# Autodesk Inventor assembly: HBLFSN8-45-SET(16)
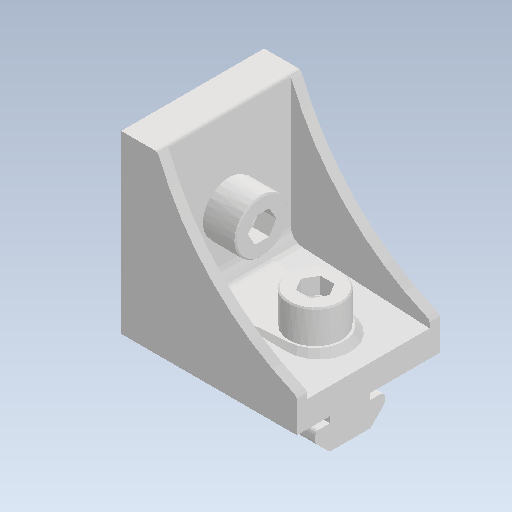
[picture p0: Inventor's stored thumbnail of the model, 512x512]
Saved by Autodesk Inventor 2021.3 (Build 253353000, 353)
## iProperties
Created: 2022-02
Part Number: HBLFSN8-45-SET(16)
Document SubType Name: Assembly
Designer: kengo
Author: kengo
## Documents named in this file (4)
- C:\Users\kengo\Documents\S2S_frame\SDC345\frame_misumi_ver12\HBLFSN8-45-SET(16).iam
- C:\Users\kengo\Documents\S2S_frame\SDC345\frame_misumi_ver12\HBLFSN8-45.ipt
- C:\Users\kengo\Documents\S2S_frame\SDC345\frame_misumi_ver12\HNTT8-8.ipt
- C:\Users\kengo\Documents\S2S_frame\SDC345\frame_misumi_ver12\CBM8-20.ipt
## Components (5 placed, 3 different names)
1. HBLFSN8-45
2. HNTT8-8
3. CBM8-20
4. HNTT8-8:1
5. CBM8-20:1
